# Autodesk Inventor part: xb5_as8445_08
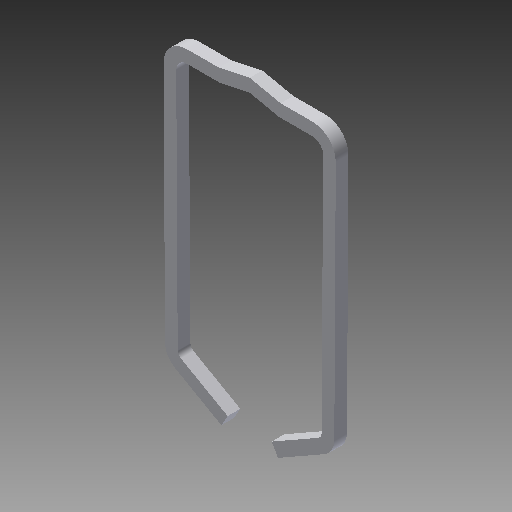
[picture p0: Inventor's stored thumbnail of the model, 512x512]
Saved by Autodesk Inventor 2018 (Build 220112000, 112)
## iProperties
Company: TraceParts S.A.
Created: 2018-04
Part Number: xb5_as8445_08
Checked By: TraceParts S.A.
Material: Generic
Catalog Web Link: www.traceparts.com
Document SubType Name: Modeling
Designer: TraceParts
Density: 1 g/cm^3
Appearance: Default
Author: TraceParts
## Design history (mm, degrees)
feature "xb5_as8445_08.ipt"
body "Solid1"
